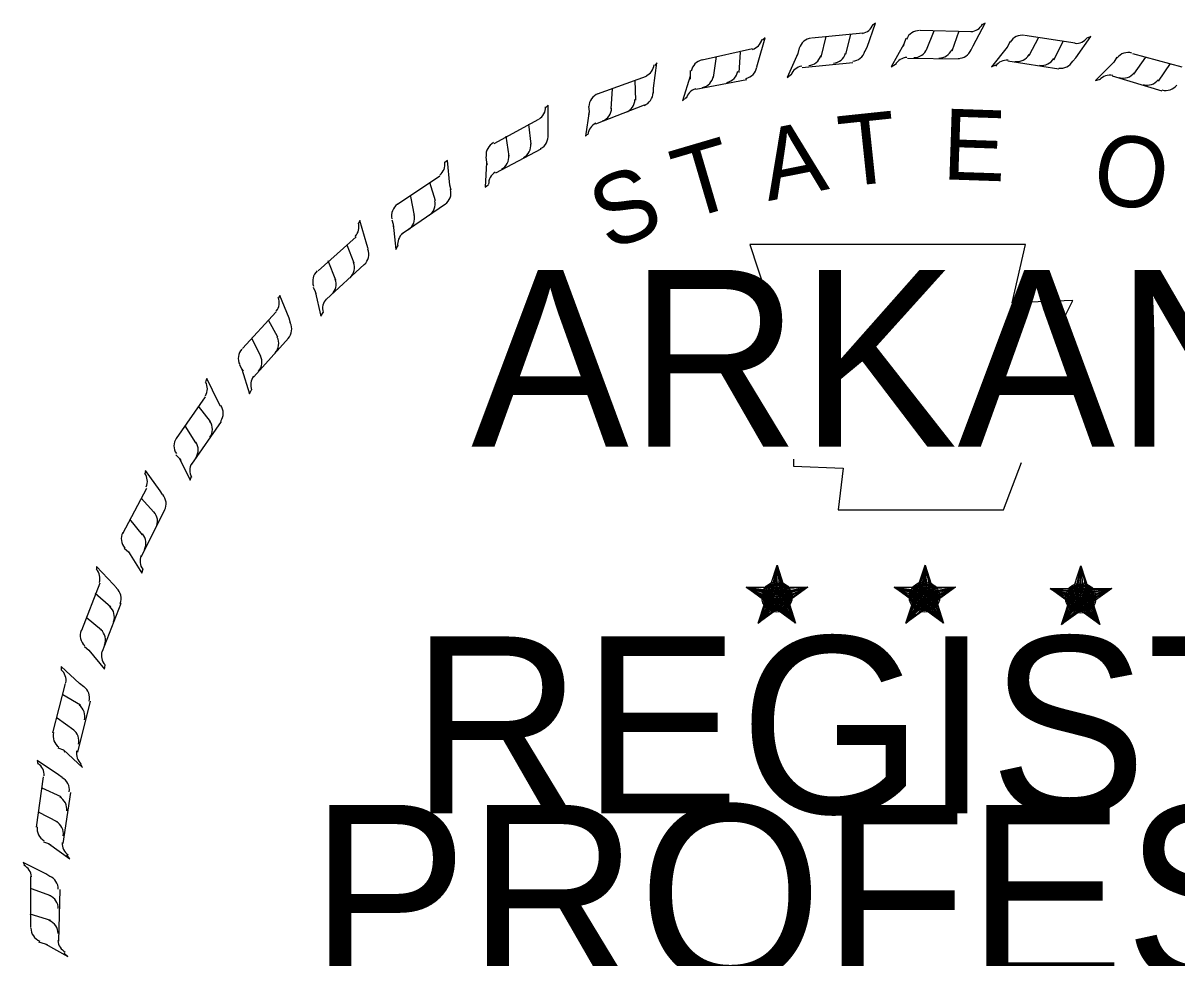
# Model space of a CAD drawing. Extents: x 208.7 to 242.8, y 328.9 to 350.7.
# Drawn here: x 233.313 to 234.537, y 331.223 to 332.214 of the extents above; entities that cross this region are included whole.
import ezdxf

# ---------------------------------------------------------------- set-up
doc = ezdxf.new("R2010")
doc.units = 0
doc.layers.add('Border 2660-Hwy18 - Stamp-ChrisC', color=7, linetype='Continuous')

msp = doc.modelspace()

# ---------------------------------------------------------------- linework, layer by layer
at = {"layer": 'Border 2660-Hwy18 - Stamp-ChrisC'}
for p, q in [((234.2082, 332.1884), (234.2172, 332.2139)), ((234.2172, 332.2139), (234.2142, 332.2116)), ((234.2644, 332.2064), (234.3184, 332.2049)), ((234.3207, 332.1899), (234.3334, 332.2139)), ((234.3334, 332.2139), (234.3304, 332.2124)), ((234.0927, 332.1726), (234.1002, 332.1981)), ((234.1002, 332.1981), (234.0972, 332.1959)), ((234.1497, 332.1981), (234.2037, 332.2034)), ((234.1594, 332.1779), (234.1647, 332.1996)), ((234.1857, 332.1809), (234.1909, 332.2019)), ((234.2494, 332.1974), (234.2472, 332.1914)), ((234.2712, 332.1854), (234.2794, 332.2056)), ((234.2982, 332.1846), (234.3057, 332.2056)), ((234.3597, 332.1944), (234.3567, 332.1884)), ((234.3754, 332.2011), (234.4287, 332.1929)), ((234.3799, 332.1794), (234.3904, 332.1989)), ((234.4062, 332.1749), (234.4159, 332.1944)), ((234.4294, 332.1771), (234.4452, 332.1996)), ((234.4452, 332.1996), (234.4422, 332.1981)), ((234.0334, 332.1749), (234.0867, 332.1869)), ((234.0724, 332.1614), (234.0739, 332.1831)), ((234.1347, 332.1816), (234.1234, 332.1561)), ((234.1347, 332.1816), (234.1339, 332.1794)), ((234.1362, 332.1876), (234.1347, 332.1816)), ((234.2059, 332.1839), (234.2082, 332.1884)), ((234.2472, 332.1914), (234.2337, 332.1674)), ((234.2472, 332.1914), (234.2464, 332.1891)), ((234.3184, 332.1854), (234.3207, 332.1899)), ((234.3567, 332.1884), (234.3402, 332.1674)), ((234.3567, 332.1884), (234.3559, 332.1869)), ((234.4894, 332.1816), (234.5419, 332.1674)), ((233.9817, 332.1449), (233.9854, 332.1719)), ((233.9854, 332.1719), (233.9832, 332.1689)), ((234.0454, 332.1561), (234.0484, 332.1786)), ((234.0912, 332.1674), (234.0927, 332.1726)), ((234.1932, 332.1719), (234.1392, 332.1666)), ((234.2337, 332.1674), (234.2382, 332.1704)), ((234.3057, 332.1756), (234.2509, 332.1764)), ((234.3402, 332.1674), (234.3447, 332.1696)), ((234.4114, 332.1651), (234.3574, 332.1734)), ((234.4264, 332.1734), (234.4294, 332.1771)), ((234.4699, 332.1726), (234.4504, 332.1531)), ((234.4699, 332.1726), (234.4684, 332.1711)), ((234.4729, 332.1779), (234.4699, 332.1726)), ((234.4909, 332.1599), (234.5037, 332.1779)), ((234.5172, 332.1524), (234.5299, 332.1711)), ((233.9224, 332.1389), (233.9742, 332.1576)), ((234.0207, 332.1576), (234.0124, 332.1314)), ((234.0207, 332.1636), (234.0207, 332.1576)), ((234.0207, 332.1576), (234.0207, 332.1546)), ((234.1234, 332.1561), (234.1279, 332.1599)), ((234.5209, 332.1419), (234.4684, 332.1576)), ((233.9629, 332.1321), (233.9622, 332.1531)), ((233.9817, 332.1396), (233.9817, 332.1449)), ((234.0807, 332.1539), (234.0267, 332.1434)), ((234.4504, 332.1531), (234.4557, 332.1546)), ((233.9367, 332.1231), (233.9382, 332.1441)), ((234.0124, 332.1314), (234.0162, 332.1351)), ((233.8699, 332.1269), (233.8677, 332.1246)), ((233.8699, 332.1006), (233.8699, 332.1269)), ((233.9127, 332.1254), (233.9134, 332.1201)), ((233.9719, 332.1269), (233.9202, 332.1066)), ((233.8129, 332.0864), (233.8602, 332.1119)), ((233.9134, 332.1201), (233.9097, 332.0939)), ((233.9134, 332.1201), (233.9127, 332.1171)), ((233.8519, 332.0856), (233.8497, 332.1066)), ((233.8699, 332.0954), (233.8699, 332.1006)), ((233.9097, 332.0939), (233.9127, 332.0969)), ((233.8287, 332.0729), (233.8257, 332.0939)), ((233.8039, 332.0721), (233.8047, 332.0661)), ((233.8624, 332.0804), (233.8144, 332.0549)), ((233.7634, 332.0684), (233.7604, 332.0661)), ((233.7657, 332.0421), (233.7634, 332.0684)), ((233.8047, 332.0661), (233.8032, 332.0399)), ((233.8047, 332.0661), (233.8054, 332.0639)), ((233.7102, 332.0219), (233.7552, 332.0519)), ((233.7507, 332.0256), (233.7447, 332.0451)), ((233.7672, 332.0369), (233.7657, 332.0421)), ((233.8032, 332.0399), (233.8069, 332.0429)), ((233.7282, 332.0099), (233.7244, 332.0301)), ((233.7612, 332.0219), (233.7154, 331.9904)), ((233.6704, 332.0046), (233.6689, 332.0016)), ((233.6779, 331.9791), (233.6704, 332.0046)), ((233.7042, 332.0054), (233.7057, 332.0009)), ((233.7057, 332.0009), (233.7087, 331.9739)), ((233.7057, 332.0009), (233.7057, 331.9979)), ((233.6262, 331.9514), (233.6667, 331.9874)), ((233.6644, 331.9596), (233.6569, 331.9784)), ((233.6794, 331.9746), (233.6779, 331.9791)), ((233.7087, 331.9739), (233.7109, 331.9784)), ((233.6449, 331.9416), (233.6367, 331.9619)), ((233.6749, 331.9581), (233.6352, 331.9214)), ((233.5857, 331.9251), (233.5842, 331.9229)), ((233.5954, 331.9011), (233.5857, 331.9251)), ((233.6209, 331.9341), (233.6232, 331.9296)), ((233.6232, 331.9296), (233.6292, 331.9034)), ((233.6232, 331.9296), (233.6239, 331.9274)), ((233.5459, 331.8689), (233.5819, 331.9079)), ((233.5969, 331.8959), (233.5954, 331.9011)), ((233.6292, 331.9034), (233.6314, 331.9071)), ((233.5834, 331.8809), (233.5737, 331.8989)), ((233.5654, 331.8606), (233.5564, 331.8794)), ((233.5947, 331.8801), (233.5579, 331.8389)), ((233.5429, 331.8516), (233.5452, 331.8471)), ((233.5452, 331.8471), (233.5534, 331.8209)), ((233.5452, 331.8471), (233.5467, 331.8449)), ((233.5084, 331.8374), (233.5069, 331.8336)), ((233.5204, 331.8126), (233.5084, 331.8374)), ((233.4762, 331.7736), (233.5069, 331.8179)), ((233.5534, 331.8209), (233.5557, 331.8254)), ((233.5122, 331.7916), (233.4994, 331.8081)), ((233.5227, 331.8081), (233.5204, 331.8126)), ((233.5234, 331.7916), (233.4919, 331.7466)), ((233.4964, 331.7691), (233.4852, 331.7871)), ((233.4754, 331.7564), (233.4792, 331.7526)), ((233.4792, 331.7526), (233.4904, 331.7294)), ((233.4792, 331.7526), (233.4807, 331.7504)), ((233.4432, 331.7399), (233.4424, 331.7361)), ((233.4589, 331.7181), (233.4432, 331.7399)), ((233.4904, 331.7294), (233.4919, 331.7339)), ((233.4192, 331.6731), (233.4447, 331.7211)), ((233.4612, 331.7144), (233.4589, 331.7181)), ((233.4522, 331.6956), (233.4387, 331.7106)), ((233.4634, 331.6979), (233.4387, 331.6484)), ((233.4402, 331.6716), (233.4267, 331.6881)), ((233.4207, 331.6574), (233.4252, 331.6536)), ((233.4252, 331.6536), (233.4394, 331.6311)), ((233.4252, 331.6536), (233.4267, 331.6514)), ((233.4094, 331.6191), (233.3914, 331.6379)), ((233.3914, 331.6379), (233.3914, 331.6349)), ((233.4394, 331.6311), (233.4409, 331.6356)), ((234.1129, 331.6394), (234.1077, 331.6169)), ((234.1129, 331.6394), (234.1092, 331.6161)), ((234.1129, 331.6394), (234.1114, 331.6161)), ((234.1129, 331.6056), (234.1129, 331.6394)), ((234.1129, 331.6394), (234.1189, 331.6161)), ((234.1129, 331.6394), (234.1174, 331.6161)), ((234.1129, 331.6394), (234.1152, 331.6161)), ((234.2697, 331.6394), (234.2637, 331.6169)), ((234.2697, 331.6394), (234.2659, 331.6161)), ((234.2697, 331.6394), (234.2674, 331.6161)), ((234.2697, 331.6056), (234.2697, 331.6394)), ((234.2697, 331.6394), (234.2757, 331.6161)), ((234.2697, 331.6394), (234.2742, 331.6161)), ((234.2697, 331.6394), (234.2712, 331.6161)), ((234.4347, 331.6386), (234.4294, 331.6154)), ((234.4347, 331.6386), (234.4309, 331.6154)), ((234.4347, 331.6386), (234.4332, 331.6154)), ((234.4347, 331.6041), (234.4347, 331.6386)), ((234.4347, 331.6386), (234.4414, 331.6154)), ((234.4347, 331.6386), (234.4399, 331.6154)), ((234.4347, 331.6386), (234.4369, 331.6154)), ((233.3757, 331.5704), (233.3952, 331.6206)), ((233.4124, 331.6154), (233.4094, 331.6191)), ((233.4064, 331.5951), (233.3899, 331.6094)), ((234.0799, 331.6161), (234.1129, 331.6056)), ((234.0799, 331.6161), (234.1039, 331.6131)), ((234.0799, 331.6161), (234.1039, 331.6116)), ((234.0799, 331.6161), (234.1032, 331.6101)), ((234.0799, 331.6161), (234.1024, 331.6064)), ((234.0799, 331.6161), (234.1024, 331.6041)), ((234.0799, 331.6161), (234.1024, 331.6019)), ((234.1452, 331.6161), (234.1129, 331.6056)), ((234.1452, 331.6161), (234.1167, 331.6139)), ((234.1452, 331.6161), (234.1189, 331.6109)), ((234.1452, 331.6161), (234.1189, 331.6094)), ((234.1452, 331.6161), (234.1249, 331.6071)), ((234.1452, 331.6161), (234.1264, 331.6064)), ((234.1452, 331.6161), (234.1279, 331.6049)), ((234.2367, 331.6161), (234.2697, 331.6056)), ((234.2367, 331.6161), (234.2607, 331.6131)), ((234.2367, 331.6161), (234.2599, 331.6116)), ((234.2367, 331.6161), (234.2599, 331.6101)), ((234.2367, 331.6161), (234.2592, 331.6064)), ((234.2367, 331.6161), (234.2584, 331.6041)), ((234.2367, 331.6161), (234.2584, 331.6019)), ((234.3019, 331.6161), (234.2697, 331.6056)), ((234.3019, 331.6161), (234.2734, 331.6139)), ((234.3019, 331.6161), (234.2749, 331.6109)), ((234.3019, 331.6161), (234.2749, 331.6094)), ((234.3019, 331.6161), (234.2809, 331.6071)), ((234.3019, 331.6161), (234.2824, 331.6064)), ((234.3019, 331.6161), (234.2839, 331.6049)), ((234.4024, 331.6146), (234.4347, 331.6041)), ((234.4024, 331.6146), (234.4264, 331.6124)), ((234.4024, 331.6146), (234.4264, 331.6109)), ((234.4024, 331.6146), (234.4249, 331.6086)), ((234.4024, 331.6146), (234.4249, 331.6056)), ((234.4024, 331.6146), (234.4242, 331.6034)), ((234.4024, 331.6146), (234.4242, 331.6011)), ((234.4677, 331.6146), (234.4347, 331.6041)), ((234.4677, 331.6146), (234.4384, 331.6124)), ((234.4677, 331.6146), (234.4407, 331.6101)), ((234.4677, 331.6146), (234.4407, 331.6086)), ((234.4677, 331.6146), (234.4467, 331.6064)), ((234.4677, 331.6146), (234.4482, 331.6049)), ((234.4677, 331.6146), (234.4497, 331.6041)), ((233.4169, 331.5989), (233.3974, 331.5479)), ((234.0927, 331.5779), (234.1129, 331.6056)), ((234.0927, 331.5779), (234.1032, 331.6034)), ((234.0927, 331.5779), (234.1047, 331.6004)), ((234.0927, 331.5779), (234.1062, 331.5996)), ((234.0927, 331.5779), (234.1129, 331.5981)), ((234.0927, 331.5779), (234.1092, 331.5974)), ((234.0927, 331.5779), (234.1129, 331.5951)), ((234.1324, 331.5779), (234.1129, 331.6056)), ((234.1324, 331.5779), (234.1129, 331.5974)), ((234.1324, 331.5779), (234.1129, 331.5951)), ((234.1324, 331.5779), (234.1159, 331.5974)), ((234.1324, 331.5779), (234.1189, 331.6004)), ((234.1324, 331.5779), (234.1197, 331.6049)), ((234.1324, 331.5779), (234.1219, 331.6049)), ((234.2494, 331.5779), (234.2697, 331.6056)), ((234.2494, 331.5779), (234.2599, 331.6034)), ((234.2494, 331.5779), (234.2607, 331.6004)), ((234.2494, 331.5779), (234.2629, 331.5996)), ((234.2494, 331.5779), (234.2689, 331.5981)), ((234.2494, 331.5779), (234.2659, 331.5974)), ((234.2494, 331.5779), (234.2697, 331.5951)), ((234.2892, 331.5779), (234.2689, 331.5974)), ((234.2892, 331.5779), (234.2689, 331.5951)), ((234.2892, 331.5779), (234.2697, 331.6056)), ((234.2892, 331.5779), (234.2727, 331.5974)), ((234.2892, 331.5779), (234.2757, 331.6004)), ((234.2892, 331.5779), (234.2764, 331.6049)), ((234.2892, 331.5779), (234.2787, 331.6049)), ((234.4144, 331.5764), (234.4347, 331.6041)), ((234.4144, 331.5764), (234.4249, 331.6019)), ((234.4144, 331.5764), (234.4264, 331.5996)), ((234.4144, 331.5764), (234.4287, 331.5989)), ((234.4144, 331.5764), (234.4347, 331.5966)), ((234.4144, 331.5764), (234.4309, 331.5959)), ((234.4144, 331.5764), (234.4354, 331.5944)), ((234.4549, 331.5764), (234.4347, 331.6041)), ((234.4549, 331.5764), (234.4347, 331.5966)), ((234.4549, 331.5764), (234.4384, 331.5959)), ((234.4549, 331.5764), (234.4414, 331.5996)), ((234.4549, 331.5764), (234.4422, 331.6034)), ((234.4549, 331.5764), (234.4444, 331.6041)), ((233.3967, 331.5704), (233.3802, 331.5839)), ((234.4549, 331.5764), (234.4347, 331.5936)), ((233.3787, 331.5531), (233.3832, 331.5494)), ((233.3832, 331.5494), (233.3997, 331.5291)), ((233.3832, 331.5494), (233.3847, 331.5479)), ((233.3997, 331.5291), (233.4004, 331.5336)), ((233.3734, 331.5141), (233.3539, 331.5321)), ((233.3539, 331.5321), (233.3539, 331.5284)), ((233.3449, 331.4616), (233.3584, 331.5141)), ((233.3779, 331.5104), (233.3734, 331.5141)), ((233.3742, 331.4909), (233.3554, 331.5021)), ((233.3847, 331.4954), (233.3712, 331.4414)), ((233.3674, 331.4646), (233.3494, 331.4774)), ((233.3502, 331.4459), (233.3562, 331.4436)), ((233.3562, 331.4436), (233.3764, 331.4249)), ((233.3562, 331.4436), (233.3577, 331.4414)), ((233.3509, 331.4174), (233.3284, 331.4324)), ((233.3284, 331.4324), (233.3292, 331.4286)), ((233.3764, 331.4249), (233.3742, 331.4294)), ((233.3277, 331.3619), (233.3352, 331.4151)), ((233.3547, 331.4144), (233.3509, 331.4174)), ((233.3539, 331.3941), (233.3337, 331.4031)), ((233.3637, 331.3986), (233.3554, 331.3446)), ((233.3502, 331.3671), (233.3299, 331.3776)), ((233.3352, 331.3461), (233.3404, 331.3446)), ((233.3404, 331.3446), (233.3629, 331.3281)), ((233.3404, 331.3446), (233.3427, 331.3431)), ((233.3629, 331.3281), (233.3599, 331.3326)), ((233.3374, 331.3124), (233.3134, 331.3244)), ((233.3134, 331.3244), (233.3149, 331.3214)), ((233.3217, 331.2554), (233.3217, 331.3094)), ((233.3419, 331.3094), (233.3374, 331.3124)), ((233.3427, 331.2891), (233.3224, 331.2966)), ((233.3524, 331.2959), (233.3509, 331.2411)), ((233.3427, 331.2629), (233.3209, 331.2696)), ((233.3299, 331.2404), (233.3367, 331.2381)), ((233.3367, 331.2381), (233.3607, 331.2246)), ((233.3367, 331.2381), (233.3389, 331.2374)), ((233.3607, 331.2246), (233.3569, 331.2284))]:
    msp.add_line(p, q, dxfattribs=at)
for points in [[(234.0837, 331.9791), (234.1092, 331.9019)], [(234.4129, 331.8929), (234.4264, 331.9199), (234.3619, 331.9176), (234.3762, 331.9791), (234.0837, 331.9791)], [(234.1302, 331.7519), (234.1302, 331.7444), (234.1827, 331.7421), (234.1774, 331.6979), (234.3529, 331.6979), (234.3717, 331.7481)], [(234.1129, 331.6394), (234.1324, 331.5779), (234.0799, 331.6161), (234.1452, 331.6161), (234.0927, 331.5779), (234.1129, 331.6394)], [(234.2697, 331.6394), (234.2892, 331.5779), (234.2367, 331.6161), (234.3019, 331.6161), (234.2494, 331.5779), (234.2697, 331.6394)], [(234.4347, 331.6386), (234.4549, 331.5764), (234.4024, 331.6146), (234.4677, 331.6146), (234.4144, 331.5764), (234.4347, 331.6386)]]:
    msp.add_lwpolyline(points, dxfattribs=at)
for centre, radius in [((234.1126, 331.6057), 0.0161), ((234.1126, 331.6057), 0.0146), ((234.1126, 331.6057), 0.0136), ((234.269, 331.6057), 0.0161), ((234.269, 331.6057), 0.0146), ((234.269, 331.6057), 0.0136), ((234.4347, 331.6046), 0.0161), ((234.4347, 331.6046), 0.0146), ((234.1126, 331.6057), 0.0124), ((234.1126, 331.6057), 0.0109), ((234.1126, 331.6057), 0.0101), ((234.1126, 331.6057), 0.00929), ((234.1126, 331.6057), 0.008), ((234.1126, 331.6057), 0.00701), ((234.1126, 331.6057), 0.00583), ((234.1126, 331.6057), 0.00464), ((234.1126, 331.6057), 0.00346), ((234.1126, 331.6057), 0.00278), ((234.1126, 331.6057), 0.00135), ((234.269, 331.6057), 0.0124), ((234.269, 331.6057), 0.0109), ((234.269, 331.6057), 0.0101), ((234.269, 331.6057), 0.00929), ((234.269, 331.6057), 0.008), ((234.269, 331.6057), 0.00701), ((234.269, 331.6057), 0.00583), ((234.269, 331.6057), 0.00464), ((234.269, 331.6057), 0.00346), ((234.269, 331.6057), 0.00278), ((234.269, 331.6057), 0.00135), ((234.4347, 331.6046), 0.0136), ((234.4347, 331.6046), 0.0124), ((234.4347, 331.6046), 0.0109), ((234.4347, 331.6046), 0.0101), ((234.4347, 331.6046), 0.00929), ((234.4347, 331.6046), 0.008), ((234.4347, 331.6046), 0.00701), ((234.4347, 331.6046), 0.00583), ((234.4347, 331.6046), 0.00464), ((234.4347, 331.6046), 0.00346), ((234.4347, 331.6046), 0.00278), ((234.4347, 331.6046), 0.00135)]:
    msp.add_circle(centre, radius, dxfattribs=at)
for centre, start, end in [((234.2006, 332.2176), 279.9249, 338.7128), ((234.2636, 332.1911), 89.1628, 157.5368), ((234.3173, 332.2196), 273.4236, 332.2115), ((234.0824, 332.2002), 286.2701, 345.0579), ((234.1505, 332.1832), 95.6641, 164.0381), ((234.3726, 332.1862), 81.4231, 149.797), ((234.4296, 332.2072), 265.6839, 324.4717), ((234.1711, 332.186), 275.6641, 344.0381), ((234.1915, 332.1881), 275.6641, 344.0381), ((234.2579, 332.1921), 269.1628, 337.5368), ((234.2843, 332.1916), 269.1628, 337.5368), ((234.3048, 332.1913), 269.1628, 337.5368), ((234.4849, 332.1679), 73.9909, 142.3649), ((233.9677, 332.1714), 294.8371, 353.6249), ((234.0364, 332.1604), 102.0093, 170.3833), ((234.1448, 332.1835), 275.6641, 344.0381), ((234.2512, 332.1628), 93.4236, 152.2115), ((234.3565, 332.1598), 85.6839, 144.4717), ((234.3671, 332.1879), 261.4231, 329.797), ((234.3932, 332.1839), 261.4231, 329.797), ((234.4135, 332.1809), 261.4231, 329.797), ((234.0306, 332.1601), 282.0093, 350.3833), ((234.0565, 332.1655), 282.0093, 350.3833), ((234.0766, 332.1698), 282.0093, 350.3833), ((234.1414, 332.1537), 99.9249, 158.7128), ((234.4655, 332.1438), 78.2517, 137.0395), ((234.4796, 332.1703), 253.9909, 322.3649), ((234.505, 332.1629), 253.9909, 322.3649), ((234.5248, 332.1573), 253.9909, 322.3649), ((233.9281, 332.1252), 110.5763, 178.9503), ((233.9473, 332.1332), 290.5763, 358.9503), ((233.9665, 332.1405), 290.5763, 358.9503), ((234.0306, 332.1301), 106.2701, 165.0579), ((233.8526, 332.1248), 301.9545, 0.7423), ((233.9225, 332.124), 290.5763, 358.9503), ((233.9269, 332.0943), 114.8371, 173.6249), ((233.819, 332.0741), 117.6937, 186.0677), ((233.837, 332.0844), 297.6937, 6.0677), ((233.8552, 332.094), 297.6937, 6.0677), ((233.8136, 332.0722), 297.6937, 6.0677), ((233.7459, 332.0643), 309.1135, 7.9014), ((233.8217, 332.0433), 121.9545, 180.7423), ((233.7523, 332.0341), 304.8528, 13.2267), ((233.7355, 332.0223), 304.8528, 13.2267), ((233.7189, 332.0098), 124.8528, 193.2267), ((233.7137, 332.0073), 304.8528, 13.2267), ((233.6547, 331.998), 316.8235, 15.6113), ((233.7253, 331.9796), 129.1135, 187.9014), ((233.6651, 331.9689), 312.5627, 20.9367), ((233.6352, 331.9404), 132.5627, 200.9367), ((233.65, 331.955), 312.5627, 20.9367), ((233.6305, 331.9372), 312.5627, 20.9367), ((233.5702, 331.9177), 322.2653, 21.0531), ((233.6457, 331.9113), 136.8235, 195.6113), ((233.5834, 331.8897), 318.0045, 26.3785), ((233.5697, 331.8744), 318.0045, 26.3785), ((233.5564, 331.8585), 138.0045, 206.3785), ((233.5519, 331.8548), 318.0045, 26.3785), ((233.5695, 331.8305), 142.2653, 201.0531), ((233.494, 331.8264), 329.9636, 28.7515), ((233.5108, 331.8004), 325.7028, 34.0768), ((233.4993, 331.7834), 325.7028, 34.0768), ((233.4882, 331.7659), 145.7028, 214.0768), ((233.4843, 331.7616), 325.7028, 34.0768), ((233.505, 331.7399), 149.9636, 208.7515), ((233.4304, 331.7282), 337.2243, 36.0121), ((233.4503, 331.7045), 332.9635, 41.3375), ((233.4411, 331.6862), 332.9635, 41.3375), ((233.4323, 331.6674), 152.9635, 221.3375), ((233.4289, 331.6627), 332.9635, 41.3375), ((233.4522, 331.6438), 157.2243, 216.0121), ((233.3801, 331.6252), 343.6465, 42.4343), ((233.4026, 331.604), 339.3857, 47.7597), ((233.3954, 331.5847), 339.3857, 47.7597), ((233.3888, 331.5651), 159.3857, 227.7597), ((233.386, 331.56), 339.3857, 47.7597), ((233.4112, 331.5438), 163.6465, 222.4343), ((233.3443, 331.5173), 350.445, 49.2329), ((233.3691, 331.4988), 346.1842, 54.5582), ((233.3642, 331.4789), 346.1842, 54.5582), ((233.36, 331.4586), 166.1842, 234.5582), ((233.3578, 331.4532), 346.1842, 54.5582), ((233.3848, 331.4401), 170.445, 229.2329), ((233.321, 331.417), 356.646, 55.4338), ((233.3477, 331.4013), 352.3852, 60.7592), ((233.345, 331.3809), 352.3852, 60.7592), ((233.343, 331.3603), 172.3852, 240.7592), ((233.3414, 331.3547), 352.3852, 60.7592), ((233.3696, 331.3446), 176.646, 235.4338), ((233.3076, 331.3082), 3.9474, 62.7352), ((233.336, 331.2961), 359.6866, 68.0606), ((233.336, 331.2755), 359.6866, 68.0606), ((233.3366, 331.2548), 179.6866, 248.0606), ((233.3357, 331.2491), 359.6866, 68.0606), ((233.365, 331.2426), 183.9474, 242.7352)]:
    msp.add_arc(centre, 0.0148, start, end, dxfattribs=at)

# ---------------------------------------------------------------- texts
for s, rotation, p in [('T', 6.0228, (234.1822, 332.0402)), ('E', 358.0732, (234.2872, 332.0484)), ('A', 11.2132, (234.1034, 332.0252)), ('O', 350.4515, (234.4439, 332.0259)), ('T', 16.4036, (234.0164, 332.0049)), ('S', 21.594, (233.9339, 331.9719))]:
    msp.add_text(s, height=0.075, rotation=rotation, dxfattribs=at).set_placement(p)
for s, height, p in [('ARKANSAS', 0.1875, (233.7884, 331.7649)), ('REGISTERED', 0.1875, (233.7247, 331.3764)), ('PROFESSIONAL', 0.187497, (233.6174, 331.1979))]:
    msp.add_text(s, height=height, dxfattribs=at).set_placement(p)

doc.saveas('drawing.dxf')
